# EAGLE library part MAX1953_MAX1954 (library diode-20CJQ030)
Maxim's MAX1953/MAX1954/MAX1957 Low-Cost, High-Frequency, Current-Mode PWM Buck Controller Description: The MAX1953/MAX1954/MAX1957 is a family of versatile, economical, synchronous current-mode, pulse-width modulation (PWM) buck controllers. These step-down controllers are targeted for applications where cost and size are critical. The MAX1953 operates at a fixed 1MHz switching frequency, thus significantly reducing external component size and cost. Additionally, excellent transient response is obtained using less output capacitance. The MAX1953 operates from low 3V to 5.5V input voltage and can supply up to 10A of output current. Selectable current limit is provided to tailor to the external MOSFETs? on-resistance for optimum cost and performance. The output voltage is adjustable from 0.8V to 0.86VIN. With the MAX1954, the drain-voltage range on the highside FET is 3V to 13.2V and is independent of the supply voltage. It operates at a fixed 300kHz switching frequency and can be used to provide up to 25A of output current with high efficiency. The output voltage is adjustable from 0.8V to 0.86VHSD. The MAX1957 features a tracking output voltage range of 0.4V to 0.86VIN and is capable of sourcing or sinking current for applications such as DDR bus termination and PowerPC?/ASIC/DSP core supplies. The MAX1957 operates from a 3V to 5.5V input voltage and at a fixed 300kHz switching frequency. The MAX1953/MAX1954/MAX1957 provide a COMP pin that can be pulled low to shut down the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
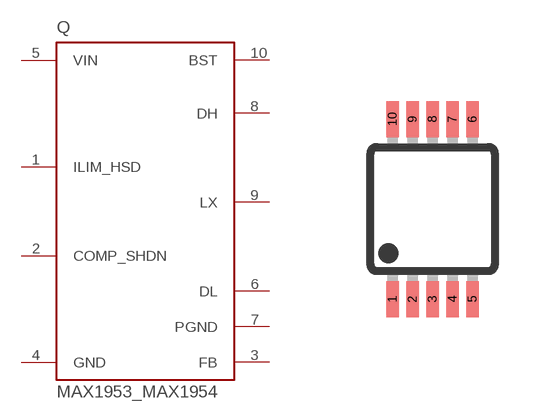
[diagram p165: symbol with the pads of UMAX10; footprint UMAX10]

Designator prefix Q

## MAX1953_MAX1954  [UMAX10]
1  ILIM_HSD  in
2  COMP_SHDN  in
3  FB  in
4  GND  pwr
5  VIN  pwr
6  DL  out
7  PGND  pwr
8  DH  out
9  LX  in
10  BST  pas

## Footprint UMAX10 (pad centres in mm)
micro MAX Package
smd 0.32 x 0.9: 1 -1,-2.25; 2 -0.5,-2.25; 3 0,-2.25; 4 0.5,-2.25; 5 1,-2.25; 6 1,2.25; 7 0.5,2.25; 8 0,2.25; 9 -0.5,2.25; 10 -1,2.25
